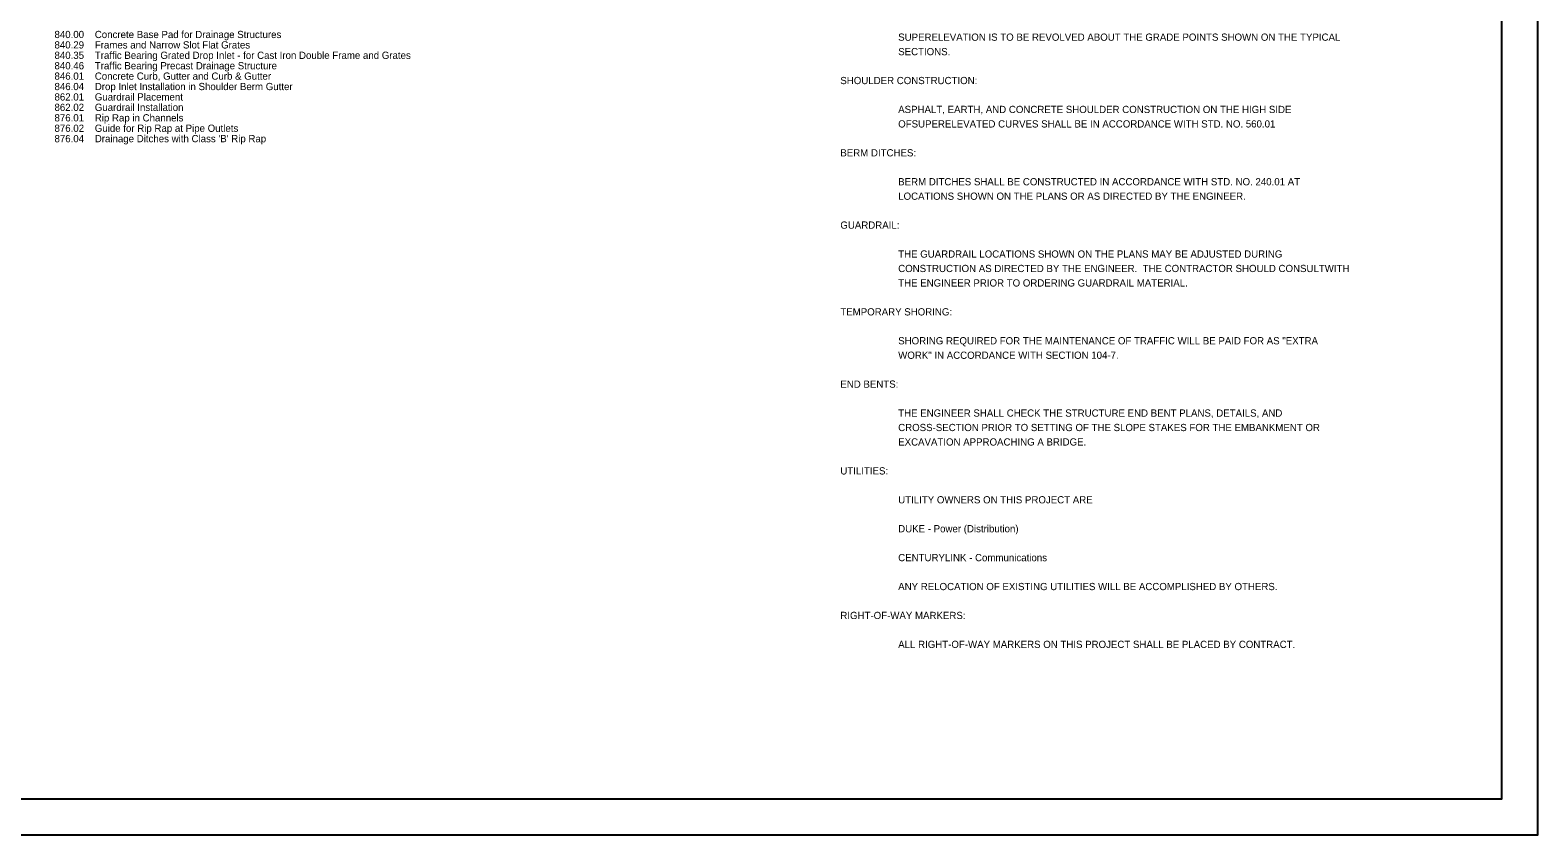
# Model space of a CAD drawing. Extents: x 972 to 1006, y 10585.8 to 10607.8.
# Drawn here: x 985.14 to 1005.99, y 10585.78 to 10596.92 of the extents above; entities that cross this region are included whole.
import ezdxf

# ---------------------------------------------------------------- set-up
doc = ezdxf.new("R2010")
doc.units = 0
for name, color, linetype in [('Sheet Data Text CELL', 7, 'Continuous'), ('Sheet Plan CELL', 7, 'Continuous'), ('Stewart Plot Border Xerox6279 and LJ5000', 7, 'Continuous')]:
    doc.layers.add(name, color=color, linetype=linetype)

msp = doc.modelspace()

# ---------------------------------------------------------------- linework, layer by layer
at = {"layer": 'Sheet Plan CELL'}
msp.add_lwpolyline([(1005.487, 10607.285), (975.487, 10607.285), (975.487, 10586.285), (1005.487, 10586.285)], close=True, dxfattribs=at)
at = {"layer": 'Stewart Plot Border Xerox6279 and LJ5000'}
msp.add_lwpolyline([(971.987, 10585.785), (1005.987, 10585.785), (1005.987, 10607.785), (971.987, 10607.785)], close=True, dxfattribs=at)

# ---------------------------------------------------------------- texts
at = {"layer": 'Sheet Data Text CELL'}
for s, p in [('840.00    Concrete Base Pad for Drainage Structures', (985.473, 10596.807)), ('840.29    Frames and Narrow Slot Flat Grates', (985.473, 10596.663)), ('SUPERELEVATION IS TO BE REVOLVED ABOUT THE GRADE POINTS SHOWN ON THE TYPICAL ', (997.141, 10596.77)), ('840.35    Traffic Bearing Grated Drop Inlet - for Cast Iron Double Frame and Grates', (985.473, 10596.519)), ('SECTIONS.  ', (997.141, 10596.57)), ('840.46    Traffic Bearing Precast Drainage Structure', (985.473, 10596.375)), ('846.01    Concrete Curb, Gutter and Curb & Gutter', (985.473, 10596.231)), ('846.04    Drop Inlet Installation in Shoulder Berm Gutter', (985.473, 10596.087)), ('SHOULDER CONSTRUCTION:  ', (996.341, 10596.17)), ('862.01    Guardrail Placement', (985.473, 10595.943)), ('862.02    Guardrail Installation', (985.473, 10595.799)), ('ASPHALT, EARTH, AND CONCRETE SHOULDER CONSTRUCTION ON THE HIGH SIDE ', (997.141, 10595.77)), ('876.01    Rip Rap in Channels', (985.473, 10595.654)), ('OFSUPERELEVATED CURVES SHALL BE IN ACCORDANCE WITH STD. NO. 560.01', (997.141, 10595.57)), ('876.02    Guide for Rip Rap at Pipe Outlets', (985.473, 10595.51)), ("876.04    Drainage Ditches with Class 'B' Rip Rap", (985.473, 10595.366)), ('BERM DITCHES:  ', (996.341, 10595.17)), ('BERM DITCHES SHALL BE CONSTRUCTED IN ACCORDANCE WITH STD. NO. 240.01 AT ', (997.141, 10594.77)), ('LOCATIONS SHOWN ON THE PLANS OR AS DIRECTED BY THE ENGINEER.  ', (997.141, 10594.57)), ('GUARDRAIL:  ', (996.341, 10594.17)), ('THE GUARDRAIL LOCATIONS SHOWN ON THE PLANS MAY BE ADJUSTED DURING ', (997.141, 10593.77)), ('CONSTRUCTION AS DIRECTED BY THE ENGINEER.  THE CONTRACTOR SHOULD CONSULTWITH ', (997.141, 10593.57)), ('THE ENGINEER PRIOR TO ORDERING GUARDRAIL MATERIAL.', (997.141, 10593.37)), ('TEMPORARY SHORING:  ', (996.341, 10592.97)), ('SHORING REQUIRED FOR THE MAINTENANCE OF TRAFFIC WILL BE PAID FOR AS "EXTRA ', (997.141, 10592.57)), ('WORK" IN ACCORDANCE WITH SECTION 104-7.  ', (997.141, 10592.37)), ('END BENTS:  ', (996.341, 10591.97)), ('THE ENGINEER SHALL CHECK THE STRUCTURE END BENT PLANS, DETAILS, AND ', (997.141, 10591.57)), ('CROSS-SECTION PRIOR TO SETTING OF THE SLOPE STAKES FOR THE EMBANKMENT OR ', (997.141, 10591.37)), ('EXCAVATION APPROACHING A BRIDGE.  ', (997.141, 10591.17)), ('UTILITIES:  ', (996.341, 10590.77)), ('UTILITY OWNERS ON THIS PROJECT ARE  ', (997.141, 10590.37)), ('DUKE - Power (Distribution)', (997.141, 10589.97)), ('CENTURYLINK - Communications', (997.141, 10589.57)), ('ANY RELOCATION OF EXISTING UTILITIES WILL BE ACCOMPLISHED BY OTHERS.  ', (997.141, 10589.17)), ('RIGHT-OF-WAY MARKERS:  ', (996.341, 10588.77)), ('ALL RIGHT-OF-WAY MARKERS ON THIS PROJECT SHALL BE PLACED BY CONTRACT.  ', (997.141, 10588.37))]:
    msp.add_text(s, height=0.1, dxfattribs=at).set_placement(p)

doc.saveas('drawing.dxf')
